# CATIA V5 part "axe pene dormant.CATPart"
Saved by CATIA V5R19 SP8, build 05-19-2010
Part number: axe pene dormant
Revision: ANY
Definition: UNKNOWN
Nomenclature: axe pene dormant
Source: Unknown
Bounding box of the stored display mesh (mm): x 0 to 12, y -2.5 to 2.5, z -2.5 to 2.5
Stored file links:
  D:\Documents\1_Travail\1 - ac-limoges.fr\ac-limoges.fr\Emmanuel Maynard - STI2D_Turgot\2 -2I2D\2_SEQUENCE_Serrure_Biométrique\5-Spé_ITEC\Serrure_Bio_Eleve\axe pene dormant.CATPart
  D:\Documents\1_Travail\1 - ac-limoges.fr\ac-limoges.fr\Emmanuel Maynard - STI2D_Turgot\2 -2I2D\2_SEQUENCE_Serrure_Biométrique\5-Spé_ITEC\Serrure_Bio_Eleve\0-serrurebio02_eleve.CATProduct
  D:\Documents\1_Travail\1 - ac-limoges.fr\ac-limoges.fr\Emmanuel Maynard - STI2D_Turgot\2 -2I2D\2_SEQUENCE_Serrure_Biométrique\5-Spé_ITEC\Serrure_Bio_Eleve\plaque guide.CATPart
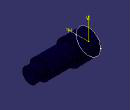
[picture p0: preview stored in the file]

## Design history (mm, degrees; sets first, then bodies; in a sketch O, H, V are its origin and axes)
Set1
  DatumSurface1: linked copy from another document
Set2
  Sketch1 on face of DatumSurface1, origin (0, 0, 0), H (0, -1, 0), V (0, 0, 1)
    projected circle E1 centre (0, 0) radius 2.5 from face of Solid1
Body1 "Révolution1" (main body)
  Solid1: solid without history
